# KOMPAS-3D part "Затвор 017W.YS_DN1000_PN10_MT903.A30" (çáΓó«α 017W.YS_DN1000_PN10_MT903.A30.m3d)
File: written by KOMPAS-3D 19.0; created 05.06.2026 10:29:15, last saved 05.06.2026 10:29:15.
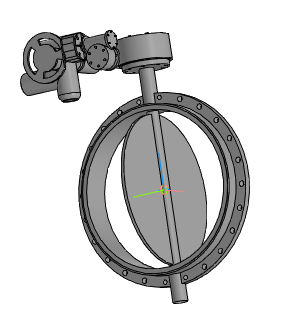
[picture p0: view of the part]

Document properties: Автор: Энергия; Полное имя файла: ..\..\..\3d для проектировщиков\x.x Тип 017W.Y(S) Затвор дисковый поворотный межфланцевый\Затвор 017W.Y(S)_DN32-DN1200_QT.A_MT903.A\Затвор 017W.YS_DN1000_PN10_MT903.A30.a3d

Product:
- Part/product: Затвор 017W.YS_DN1000_PN10_MT903.A30
    Масса: 812.324

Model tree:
1. Операция без истории:1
